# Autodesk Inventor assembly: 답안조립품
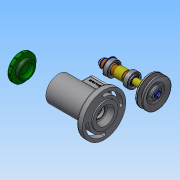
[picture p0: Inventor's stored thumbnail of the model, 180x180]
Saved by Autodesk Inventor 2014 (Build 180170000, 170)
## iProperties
Created: 2017-05
Part Number: 답안조립품
Document SubType Name: Assembly
Designer: NET
Author: NET
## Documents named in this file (19)
- C:\Users\NET\Desktop\470507V1016\답안조립품.iam
- C:\Users\NET\Desktop\470507V1016\답안부품.ipt
- C:\Users\NET\Desktop\470507V1016\축.ipt
- C:\Users\NET\Desktop\470507V1016\키 4 x 4 x 18.ipt
- C:\Users\NET\Desktop\470507V1016\V-벨트풀리.ipt
- C:\Users\NET\Desktop\470507V1016\볼트 M4 x 10.ipt
- C:\Users\NET\Desktop\470507V1016\와셔 4x16.ipt
- C:\Users\NET\Desktop\470507V1016\사이드 커버.ipt
- 사이드 커버.ipt
- C:\Users\NET\Desktop\470507V1016\너트 M10.ipt
- C:\Users\NET\Desktop\470507V1016\와셔 10x21.ipt
- C:\Users\NET\Desktop\470507V1016\멈춤링 35x1.6.ipt
- C:\Users\NET\Desktop\470507V1016\부시1.ipt
- C:\Users\NET\Desktop\470507V1016\베어링 15 x 35 x 11.ipt
- C:\Users\NET\Desktop\470507V1016\부시2.ipt
- C:\Users\NET\Desktop\470507V1016\멈춤링 15 x 1.ipt
- C:\Users\NET\Desktop\470507V1016\탑 커버.ipt
- C:\Users\NET\Desktop\470507V1016\와셔 3x6.ipt
- C:\Users\NET\Desktop\470507V1016\십자볼트 M3 x 10.ipt
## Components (2 placed, 2 different names)
1. V-벨트풀리:1
2. ISO 4017 M4 x 10:1
